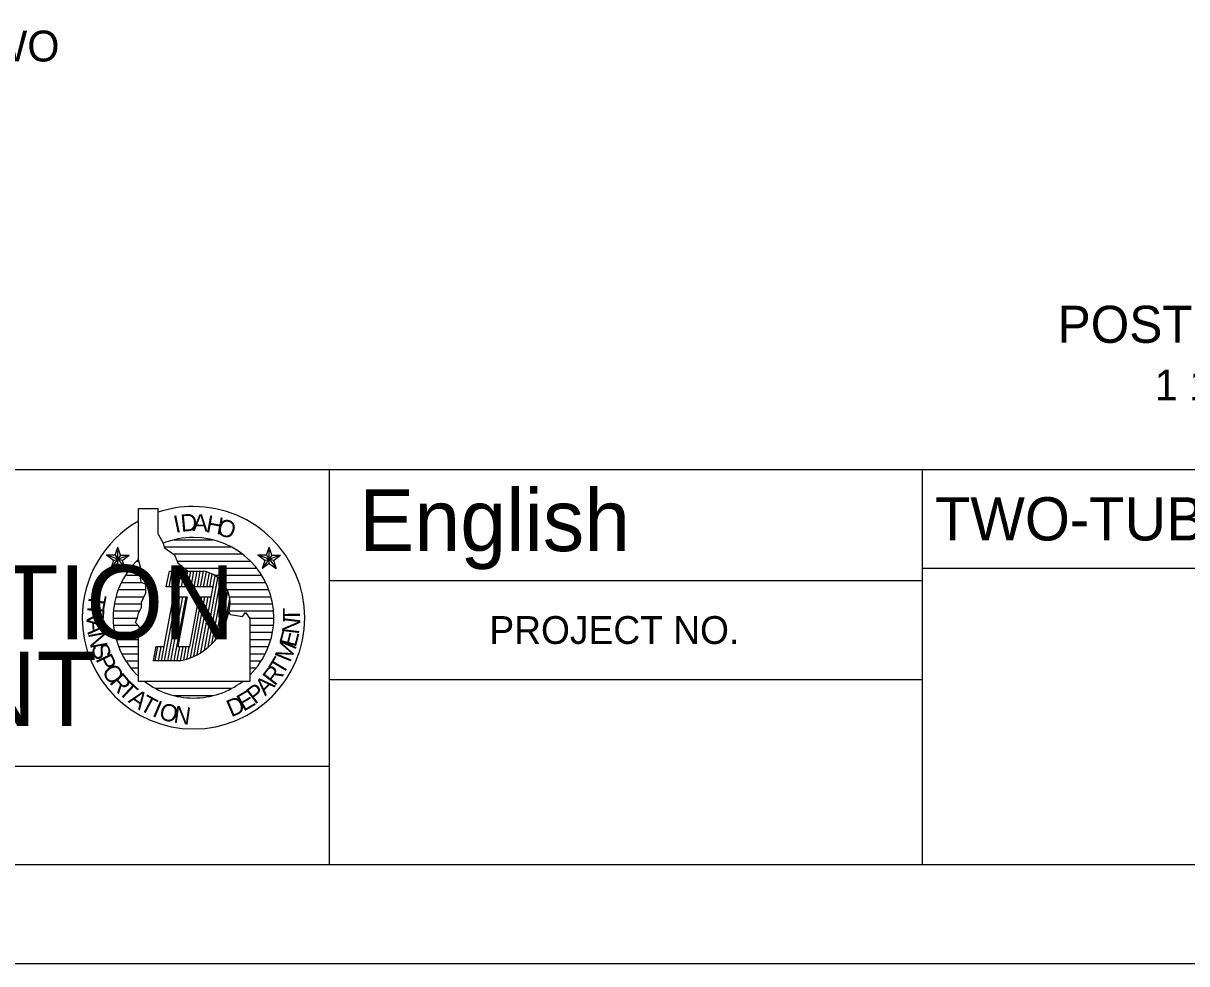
# Model space of a CAD drawing. Extents: x 0 to 45.3, y 0 to 31.4.
# Drawn here: x 23.6 to 31.45, y 0 to 6.34 of the extents above; entities that cross this region are included whole.
import ezdxf

# ---------------------------------------------------------------- set-up
doc = ezdxf.new("R2010")
doc.units = 0
for name, color, linetype in [('BORDER_ANNO_Cutsheet', 7, 'Continuous'), ('BRDG_ANNO_Anno-Sheet', 7, 'Continuous'), ('BRDG_ANNO_General-Notes', 7, 'Continuous')]:
    doc.layers.add(name, color=color, linetype=linetype)

msp = doc.modelspace()

# ---------------------------------------------------------------- linework, layer by layer
at = {"layer": 'BORDER_ANNO_Cutsheet'}
msp.add_lwpolyline([(0, 29.3333), (45.3333, 29.3333), (45.3333, 0), (0, 0)], close=True, dxfattribs=at)
at = {"layer": 'BRDG_ANNO_Anno-Sheet'}
for p, q in [((2, 3.3333), (25.6667, 3.3333)), ((25.6667, 0.6667), (25.6667, 3.3333)), ((25.6667, 3.3333), (44.6667, 3.3333)), ((29.6667, 0.6667), (29.6667, 3.3333)), ((24.3792, 2.7233), (24.3792, 3.0708)), ((24.3792, 3.0708), (24.5108, 3.0708)), ((24.5108, 2.8975), (24.5108, 3.0708)), ((24.5108, 2.8975), (24.5458, 2.835)), ((24.5458, 2.835), (24.5525, 2.8067)), ((24.62, 2.8592), (24.8775, 2.8592)), ((24.2683, 2.72), (24.1633, 2.7542)), ((24.2208, 2.7542), (24.1633, 2.7542)), ((24.21, 2.72), (24.1633, 2.7542)), ((24.2575, 2.7542), (24.1917, 2.6642)), ((24.21, 2.72), (24.3158, 2.7542)), ((24.2208, 2.7542), (24.2392, 2.8092)), ((24.2208, 2.7542), (24.2867, 2.6642)), ((24.2392, 2.6983), (24.2392, 2.8092)), ((24.2575, 2.7542), (24.2392, 2.8092)), ((24.2575, 2.7542), (24.3158, 2.7542)), ((24.2683, 2.72), (24.3158, 2.7542)), ((24.5525, 2.8067), (24.6217, 2.7583)), ((24.5558, 2.8108), (25.0008, 2.8108)), ((24.62, 2.7633), (25.0758, 2.7633)), ((24.6217, 2.7583), (24.6433, 2.7025)), ((25.29, 2.72), (25.1842, 2.7542)), ((25.2317, 2.72), (25.1842, 2.7542)), ((25.2425, 2.7542), (25.1842, 2.7542)), ((25.2792, 2.7542), (25.2133, 2.6642)), ((25.2317, 2.72), (25.3367, 2.7542)), ((25.2425, 2.7542), (25.2608, 2.8092)), ((25.2425, 2.7542), (25.3083, 2.6642)), ((25.2608, 2.6983), (25.2608, 2.8092)), ((25.2792, 2.7542), (25.2608, 2.8092)), ((25.2792, 2.7542), (25.3367, 2.7542)), ((25.29, 2.72), (25.3367, 2.7542)), ((24.21, 2.72), (24.1917, 2.6642)), ((24.2392, 2.6983), (24.1917, 2.6642)), ((24.2392, 2.6983), (24.2867, 2.6642)), ((24.2683, 2.72), (24.2867, 2.6642)), ((24.3658, 2.715), (24.3817, 2.715)), ((24.3925, 2.675), (24.3792, 2.7233)), ((24.3925, 2.6333), (24.3925, 2.675)), ((24.6383, 2.715), (25.1342, 2.715)), ((24.6433, 2.7025), (24.7125, 2.6475)), ((25.2317, 2.72), (25.2133, 2.6642)), ((25.2608, 2.6983), (25.2133, 2.6642)), ((25.2608, 2.6983), (25.3083, 2.6642)), ((25.29, 2.72), (25.3083, 2.6642)), ((24.2892, 2.6192), (24.39, 2.6192)), ((24.3225, 2.6675), (24.3917, 2.6675)), ((24.3925, 2.5983), (24.3925, 2.6333)), ((24.4, 2.5708), (24.3925, 2.5983)), ((24.5667, 2.5425), (24.5875, 2.6475)), ((24.5858, 2.5425), (24.605, 2.6475)), ((24.5875, 2.6475), (24.8167, 2.6475)), ((24.6067, 2.5425), (24.6267, 2.6475)), ((24.6283, 2.5425), (24.6475, 2.6475)), ((24.6492, 2.5425), (24.6692, 2.6475)), ((24.67, 2.5425), (24.69, 2.6475)), ((24.6875, 2.6675), (25.1767, 2.6675)), ((24.6917, 2.5425), (24.7108, 2.6475)), ((24.7125, 2.5425), (24.7325, 2.6475)), ((24.7342, 2.5425), (24.7533, 2.6475)), ((24.755, 2.5425), (24.775, 2.6475)), ((24.7767, 2.5425), (24.7958, 2.6475)), ((24.7975, 2.5425), (24.8175, 2.6475)), ((24.7992, 2.0992), (24.8958, 2.6158)), ((24.8183, 2.5425), (24.8375, 2.6417)), ((24.8233, 2.1142), (24.915, 2.6025)), ((24.84, 2.5425), (24.8575, 2.6358)), ((24.8608, 2.5425), (24.8767, 2.6267)), ((24.8917, 2.6192), (25.21, 2.6192)), ((29.6667, 2.6667), (40.3333, 2.6667)), ((24.2417, 2.5233), (24.425, 2.5233)), ((24.2625, 2.5708), (24.3975, 2.5708)), ((24.4275, 2.5567), (24.4, 2.5708)), ((24.4275, 2.5217), (24.4275, 2.5567)), ((24.4275, 2.5008), (24.4275, 2.5217)), ((24.8817, 2.5425), (24.5667, 2.5425)), ((24.8483, 2.1342), (24.9325, 2.585)), ((24.8692, 2.4733), (24.8817, 2.5425)), ((24.8742, 2.1583), (24.95, 2.5658)), ((24.9008, 2.1867), (24.9667, 2.5417)), ((24.9467, 2.5708), (25.2367, 2.5708)), ((24.9767, 2.5233), (25.2575, 2.5233)), ((25.6667, 2.5833), (29.6667, 2.5833)), ((24.2275, 2.475), (24.415, 2.475)), ((24.4, 2.4383), (24.4133, 2.4667)), ((24.4, 2.4042), (24.4, 2.4383)), ((24.4133, 2.4667), (24.4275, 2.5008)), ((24.5525, 2.14), (24.615, 2.4733)), ((24.555, 2.0425), (24.6358, 2.4733)), ((24.5767, 2.0425), (24.6575, 2.4733)), ((24.5975, 2.0425), (24.6783, 2.4733)), ((24.615, 2.4733), (24.7067, 2.4733)), ((24.6192, 2.0425), (24.7, 2.4733)), ((24.7067, 2.4733), (24.6442, 2.14)), ((24.725, 2.14), (24.7875, 2.4733)), ((24.7292, 2.0633), (24.8058, 2.4733)), ((24.7517, 2.0733), (24.8267, 2.4733)), ((24.775, 2.0842), (24.8483, 2.4733)), ((24.7875, 2.4733), (24.8692, 2.4733)), ((24.9292, 2.225), (24.9825, 2.5092)), ((24.9625, 2.29), (24.9942, 2.46)), ((24.9925, 2.475), (25.2725, 2.475)), ((24.21, 2.3792), (24.3875, 2.3792)), ((24.2167, 2.4275), (24.3975, 2.4275)), ((24.3717, 2.3342), (24.3792, 2.3625)), ((24.3792, 2.3625), (24.4, 2.4042)), ((24.9875, 2.37), (24.9975, 2.355)), ((24.99, 2.3792), (25.29, 2.3792)), ((24.9967, 2.4275), (25.2833, 2.4275)), ((24.9975, 2.355), (25.0392, 2.3483)), ((25.0808, 2.3417), (25.1017, 2.3692)), ((25.1017, 2.3692), (25.1292, 2.3275)), ((24.2083, 2.3308), (24.37, 2.3308)), ((24.2108, 2.2833), (24.375, 2.2833)), ((24.3583, 2.3), (24.3717, 2.3342)), ((24.3792, 2.2792), (24.3583, 2.3)), ((24.3925, 2.2583), (24.3792, 2.2792)), ((25.0392, 2.3483), (25.0808, 2.3417)), ((25.1267, 2.3308), (25.2917, 2.3308)), ((25.1292, 2.3275), (25.1292, 1.9033)), ((25.13, 2.2833), (25.2892, 2.2833)), ((24.2175, 2.235), (24.3975, 2.235)), ((24.3792, 2.2025), (24.4, 2.2233)), ((24.3792, 1.9033), (24.3792, 2.2025)), ((24.4, 2.2442), (24.3925, 2.2583)), ((24.4, 2.2233), (24.4, 2.2442)), ((25.1292, 2.235), (25.2825, 2.235)), ((24.2283, 2.1875), (24.3783, 2.1875)), ((24.245, 2.1392), (24.3767, 2.1392)), ((24.4792, 2.0425), (24.4975, 2.14)), ((24.4917, 2.0425), (24.51, 2.14)), ((24.4975, 2.14), (24.5525, 2.14)), ((24.5133, 2.0425), (24.5317, 2.14)), ((24.5342, 2.0425), (24.5525, 2.14)), ((24.64, 2.0425), (24.6583, 2.14)), ((24.6442, 2.14), (24.725, 2.14)), ((24.6617, 2.0433), (24.68, 2.14)), ((24.6842, 2.0492), (24.7008, 2.14)), ((24.7067, 2.0558), (24.7217, 2.14)), ((25.1292, 2.1875), (25.2717, 2.1875)), ((25.1292, 2.1392), (25.255, 2.1392)), ((24.2658, 2.0908), (24.3767, 2.0908)), ((24.2933, 2.0433), (24.3775, 2.0433)), ((24.6567, 2.0425), (24.4792, 2.0425)), ((25.1292, 2.0908), (25.2333, 2.0908)), ((25.1292, 2.0433), (25.2067, 2.0433)), ((24.3275, 1.995), (24.3767, 1.995)), ((25.1292, 1.995), (25.1733, 1.995)), ((24.37, 1.9475), (24.3783, 1.9475)), ((25.1292, 1.9033), (24.3792, 1.9033)), ((25.6667, 1.9167), (29.6667, 1.9167)), ((25.0008, 1.855), (24.4958, 1.855)), ((24.8783, 1.8075), (24.6233, 1.8075)), ((18.6667, 1.3333), (25.6667, 1.3333))]:
    msp.add_line(p, q, dxfattribs=at)
msp.add_lwpolyline([(2, 28.6667), (44.6667, 28.6667), (44.6667, 0.6667), (2, 0.6667)], close=True, dxfattribs=at)
for centre, radius, start, end in [((24.75, 2.3333), 0.75, 90, 108.596), ((24.75, 2.3333), 0.75, 0, 90), ((24.75, 2.3333), 0.75, 119.63312, 180), ((24.75, 2.3333), 0.5417, 90, 112.14518), ((24.75, 2.3333), 0.5417, 0, 90), ((24.75, 2.3333), 0.5417, 133.19257, 180), ((24.7777, 2.4322), 0.2188, 343.49805, 79.73615), ((24.5799, 2.4509), 0.4156, 280.64795, 348.77185), ((24.75, 2.3333), 0.75, 180, 270), ((24.75, 2.3333), 0.5417, 180.26444, 226.79463), ((24.75, 2.3333), 0.75, 270, 0), ((24.75, 2.3333), 0.5417, 314.427, 0), ((24.75, 2.3333), 0.5417, 232.5658, 270), ((24.75, 2.3333), 0.5417, 270, 307.45359)]:
    msp.add_arc(centre, radius, start, end, dxfattribs=at)

# ---------------------------------------------------------------- texts
for s, height, p in [('English', 0.41667, (25.8675, 2.7825)), ('TWO-TUBE CURB MOUNT RAIL W/THRIE BEAM END CONNECTION - SHT. 1 OF 2', 0.291667, (29.751, 2.8542)), ('TRANSPORTATION', 0.5, (18.8625, 2.1875)), ('PROJECT NO.', 0.1875, (26.7455, 2.1567)), ('DEPARTMENT', 0.5, (19.4925, 1.6042))]:
    msp.add_text(s, height=height, dxfattribs=at).set_placement(p)
for s, rotation, p in [('I', 11.95188, (24.6292, 2.9042)), ('D', 5.21184, (24.6683, 2.9125)), ('A', 357.8718, (24.7425, 2.9175)), ('H', 349.63177, (24.8292, 2.9117)), ('O', 342.19173, (24.8992, 2.8975)), ('T', 259.42648, (24.0508, 2.5008)), ('R', 266.0275, (24.035, 2.41)), ('T', 90.49256, (25.4692, 2.3058)), ('A', 273.76404, (24.0308, 2.3208)), ('N', 83.19321, (25.46, 2.2175)), ('N', 280.37584, (24.0383, 2.2283)), ('E', 75.61046, (25.4392, 2.1292)), ('S', 287.92792, (24.0575, 2.1383)), ('M', 67.71394, (25.4008, 2.0275)), ('P', 295.49755, (24.0875, 2.0542)), ('T', 59.03624, (25.3517, 1.94)), ('O', 302.64464, (24.1275, 1.9733)), ('R', 52.33438, (25.2983, 1.8683)), ('R', 309.90789, (24.1783, 1.8967)), ('T', 317.1211, (24.2367, 1.8283)), ('P', 37.66562, (25.1642, 1.7458)), ('A', 45, (25.2342, 1.8008)), ('A', 324.63754, (24.3042, 1.7675)), ('T', 331.75026, (24.3792, 1.7158)), ('E', 30.54757, (25.0875, 1.6983)), ('I', 337.0213, (24.4658, 1.6717)), ('O', 343.32869, (24.51, 1.6542)), ('N', 351.65981, (24.6117, 1.6267)), ('D', 22.98872, (25.0042, 1.6608))]:
    msp.add_text(s, height=0.1158, rotation=rotation, dxfattribs=at).set_placement(p)
at = {"layer": 'BRDG_ANNO_General-Notes'}
for s, height, p in [('TO BOLT HEAD TWO', 0.208333, (21.0754, 6.0843)), ('POST DETAILS', 0.25, (30.5783, 4.1872)), ('1 1/2"=1\'-0"', 0.208333, (31.2333, 3.7983))]:
    msp.add_text(s, height=height, dxfattribs=at).set_placement(p)

doc.saveas('drawing.dxf')
